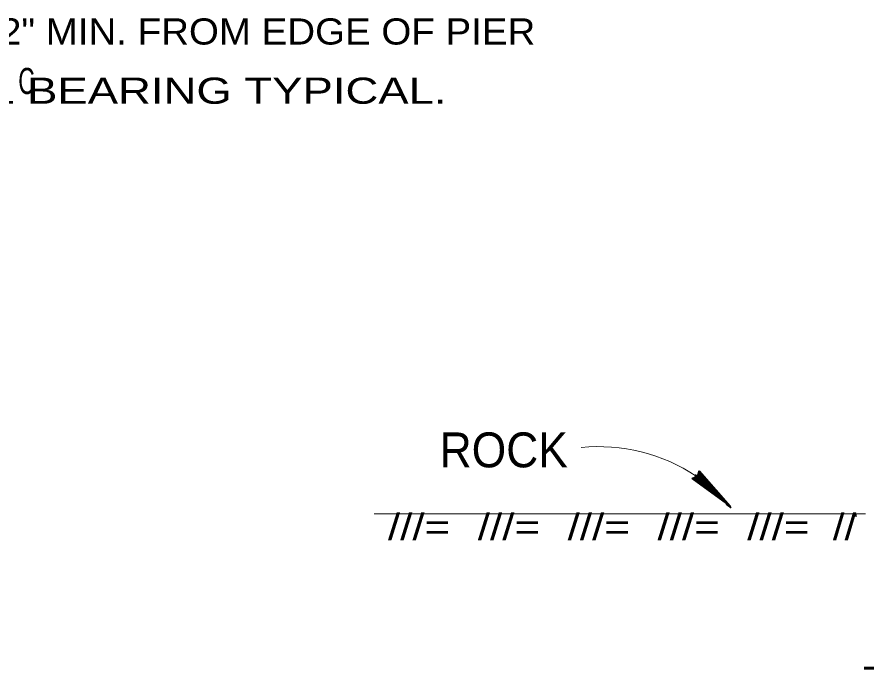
# Model space of a CAD drawing. Extents: x 1.6 to 19.9, y 2.8 to 9.5.
# Drawn here: x 18.2453 to 18.624, y 8.1814 to 8.4718 of the extents above; entities that cross this region are included whole.
import ezdxf
from ezdxf.enums import TextEntityAlignment as Align

# ---------------------------------------------------------------- set-up
doc = ezdxf.new("R2010")
doc.units = 0
doc.header["$LTSCALE"] = 0.0047
doc.layers.add('1', color=7, linetype='Continuous', lineweight=35)
doc.layers.add('5', color=7, linetype='Continuous', lineweight=13)

msp = doc.modelspace()

# ---------------------------------------------------------------- linework, layer by layer
at = {"layer": '1'}
for p, q in [((18.549667, 8.268833), (18.560083, 8.257167)), ((18.54975, 8.268917), (18.560083, 8.25725)), ((18.547, 8.265917), (18.558833, 8.257333)), ((18.547083, 8.266), (18.558917, 8.2575)), ((18.54725, 8.26625), (18.559, 8.257667)), ((18.547417, 8.2665), (18.559167, 8.257917)), ((18.548, 8.267667), (18.5635, 8.253583)), ((18.549167, 8.267), (18.556167, 8.26075)), ((18.549333, 8.268583), (18.55975, 8.256917)), ((18.5495, 8.26875), (18.559917, 8.257)), ((18.549583, 8.26875), (18.559917, 8.257167))]:
    msp.add_line(p, q, dxfattribs=at)
at = {"layer": '1', "lineweight": 60}
msp.add_line((18.623167, 8.181417), (19.00225, 8.181583), dxfattribs=at)
at = {"layer": '1'}
msp.add_lwpolyline([(18.549583, 8.269417), (18.5635, 8.253583), (18.546417, 8.266), (18.548917, 8.267)], close=True, dxfattribs=at)
for points in [[(18.561333, 8.255417), (18.548917, 8.266583), (18.55225, 8.263083), (18.5485, 8.2665), (18.556833, 8.26), (18.548167, 8.26625), (18.54925, 8.266833), (18.549583, 8.2685), (18.54975, 8.268), (18.549417, 8.267), (18.549917, 8.267), (18.550167, 8.267667), (18.548917, 8.266833), (18.548, 8.266417), (18.547, 8.266)], [(18.55475, 8.261917), (18.54925, 8.267), (18.553917, 8.263167), (18.549333, 8.2675), (18.552667, 8.264667), (18.549417, 8.267833), (18.554333, 8.262583)], [(18.556833, 8.260083), (18.5635, 8.253583), (18.561667, 8.2545), (18.563833, 8.252917)], [(18.558667, 8.25825), (18.5585, 8.258167), (18.55725, 8.259417)]]:
    msp.add_lwpolyline(points, dxfattribs=at)
at = {"layer": '1', "lineweight": 13}
msp.add_arc((18.504776, 8.201766), 0.078393, 56.26433, 95.70423, dxfattribs=at)
at = {"layer": '5'}
msp.add_line((18.404667, 8.25025), (18.623833, 8.25025), dxfattribs=at)
at = {"layer": '5', "lineweight": 25}
msp.add_line((18.6195, 8.25025), (18.6195, 8.248833), dxfattribs=at)

# ---------------------------------------------------------------- texts
at = {"layer": '1'}
for s, width, p in [('NOTE: 8 1/2" MIN. FROM EDGE OF PIER', 1.1, (18.4765, 8.4595)), ('C', 0.65, (18.253167, 8.437417)), ('  TO  L BEARING TYPICAL.', 1.3, (18.436917, 8.433083))]:
    msp.add_text(s, height=0.01167, dxfattribs=dict(at, width=width)).set_placement(p, align=Align.RIGHT)
at = {"layer": '5', "width": 0.95}
msp.add_text('ROCK', height=0.01558, dxfattribs=at).set_placement((18.433833, 8.270917))
at = {"layer": '5'}
for s, width, p in [('///=', 1.25, (18.424667, 8.2385)), ('///=', 1.25, (18.46475, 8.2385)), ('///=', 1.25, (18.504833, 8.2385)), ('///=', 1.25, (18.544917, 8.2385)), ('///=', 1.25, (18.584958, 8.2385)), ('//', 1.2, (18.614458, 8.2385))]:
    msp.add_text(s, height=0.01175, dxfattribs=dict(at, width=width)).set_placement(p, align=Align.CENTER)

doc.saveas('drawing.dxf')
